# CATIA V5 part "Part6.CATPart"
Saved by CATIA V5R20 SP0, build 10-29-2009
Part number: 9FP1205M4
Revision: ANY
Definition: UNKNOWN
Nomenclature: 9FP1205M4
Source: Unknown
Bounding box of the stored display mesh (mm): x -5.752 to 5.752, y 0 to 5, z -5.9 to 5.9
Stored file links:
  C:\Users\Utente\Desktop\IO LAVORO\3D X SITO CF\CUMSA\3D files PW\pw060630\pw060630_injection\Part6.CATPart
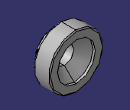
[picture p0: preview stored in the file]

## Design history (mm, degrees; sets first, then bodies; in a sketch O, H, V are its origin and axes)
Body1 "Redondeo2" (main body)
  Solid1: solid without history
